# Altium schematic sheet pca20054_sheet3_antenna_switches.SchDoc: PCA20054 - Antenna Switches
size A2; Organization: Nordic Semiconductor; DocumentNumber: 0; Revision: 1.0.0; SheetNumber: 3; SheetTotal: 5; CompanyName: Nordic Semiconductor; DrawnBy: KJP; DocumentSize: A2; Project Number: 4467
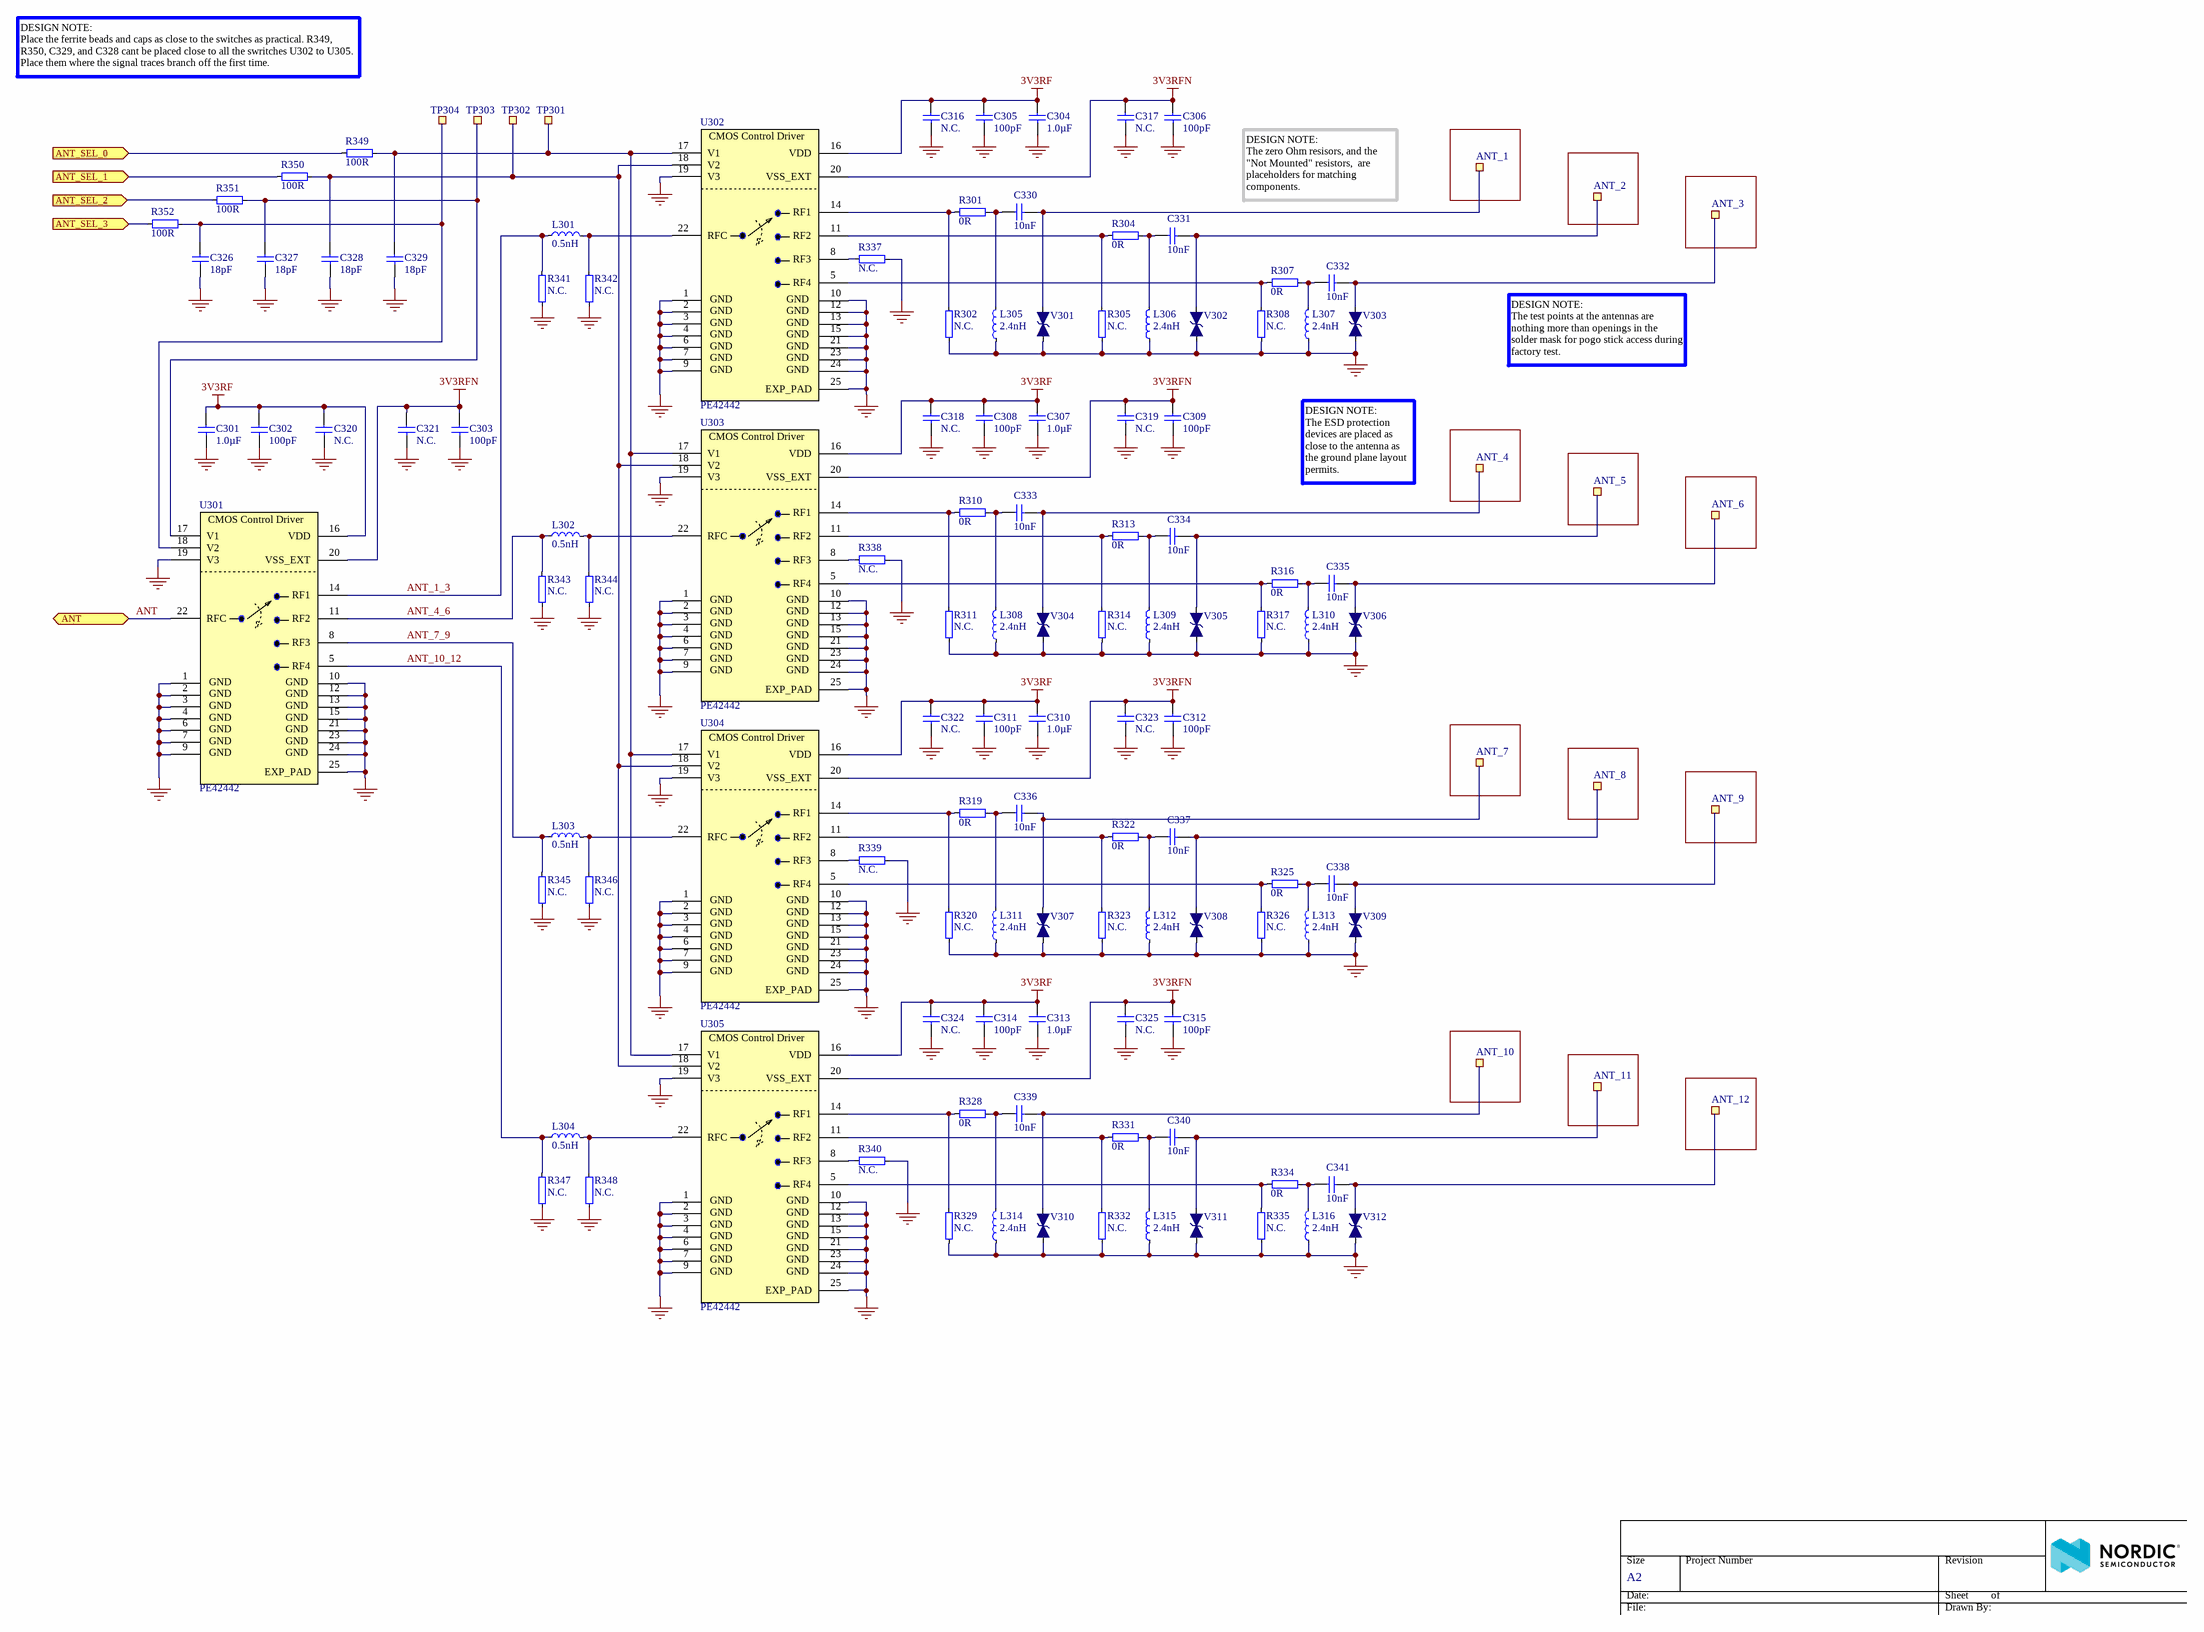
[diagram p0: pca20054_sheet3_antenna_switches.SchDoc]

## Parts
ANT_1  Ø1.0mm,SMD  [TP_SMD_Ø1.0mm]  (value not drawn)  (no BOM)
ANT_2  Ø1.0mm,SMD  [TP_SMD_Ø1.0mm]  (value not drawn)  (no BOM)
ANT_3  Ø1.0mm,SMD  [TP_SMD_Ø1.0mm]  (value not drawn)  (no BOM)
ANT_4  Ø1.0mm,SMD  [TP_SMD_Ø1.0mm]  (value not drawn)  (no BOM)
ANT_5  Ø1.0mm,SMD  [TP_SMD_Ø1.0mm]  (value not drawn)  (no BOM)
ANT_6  Ø1.0mm,SMD  [TP_SMD_Ø1.0mm]  (value not drawn)  (no BOM)
ANT_7  Ø1.0mm,SMD  [TP_SMD_Ø1.0mm]  (value not drawn)  (no BOM)
ANT_8  Ø1.0mm,SMD  [TP_SMD_Ø1.0mm]  (value not drawn)  (no BOM)
ANT_9  Ø1.0mm,SMD  [TP_SMD_Ø1.0mm]  (value not drawn)  (no BOM)
ANT_10  Ø1.0mm,SMD  [TP_SMD_Ø1.0mm]  (value not drawn)  (no BOM)
ANT_11  Ø1.0mm,SMD  [TP_SMD_Ø1.0mm]  (value not drawn)  (no BOM)
ANT_12  Ø1.0mm,SMD  [TP_SMD_Ø1.0mm]  (value not drawn)  (no BOM)
C301  1.0µF  [CAPC1608X06L]
C302  100pF  [CAPC1005X04L]
C303  100pF  [CAPC1005X04L]
C304  1.0µF  [CAPC1608X06L]
C305  100pF  [CAPC1005X04L]
C306  100pF  [CAPC1005X04L]
C307  1.0µF  [CAPC1608X06L]
C308  100pF  [CAPC1005X04L]
C309  100pF  [CAPC1005X04L]
C310  1.0µF  [CAPC1608X06L]
C311  100pF  [CAPC1005X04L]
C312  100pF  [CAPC1005X04L]
C313  1.0µF  [CAPC1608X06L]
C314  100pF  [CAPC1005X04L]
C315  100pF  [CAPC1005X04L]
C316  N.C.  [CAPC1005X04L_NC]
C317  N.C.  [CAPC1005X04L_NC]
C318  N.C.  [CAPC1005X04L_NC]
C319  N.C.  [CAPC1005X04L_NC]
C320  N.C.  [CAPC1005X04L_NC]
C321  N.C.  [CAPC1005X04L_NC]
C322  N.C.  [CAPC1005X04L_NC]
C323  N.C.  [CAPC1005X04L_NC]
C324  N.C.  [CAPC1005X04L_NC]
C325  N.C.  [CAPC1005X04L_NC]
C326  18pF  [CAPC1005X04L]
C327  18pF  [CAPC1005X04L]
C328  18pF  [CAPC1005X04L]
C329  18pF  [CAPC1005X04L]
C330  10nF  [CAPC1005X04L]
C331  10nF  [CAPC1005X04L]
C332  10nF  [CAPC1005X04L]
C333  10nF  [CAPC1005X04L]
C334  10nF  [CAPC1005X04L]
C335  10nF  [CAPC1005X04L]
C336  10nF  [CAPC1005X04L]
C337  10nF  [CAPC1005X04L]
C338  10nF  [CAPC1005X04L]
C339  10nF  [CAPC1005X04L]
C340  10nF  [CAPC1005X04L]
C341  10nF  [CAPC1005X04L]
L301  0.5nH  [INDC1005X04L]
L302  0.5nH  [INDC1005X04L]
L303  0.5nH  [INDC1005X04L]
L304  0.5nH  [INDC1005X04L]
L305  2.4nH  [INDC1005X04L]
L306  2.4nH  [INDC1005X04L]
L307  2.4nH  [INDC1005X04L]
L308  2.4nH  [INDC1005X04L]
L309  2.4nH  [INDC1005X04L]
L310  2.4nH  [INDC1005X04L]
L311  2.4nH  [INDC1005X04L]
L312  2.4nH  [INDC1005X04L]
L313  2.4nH  [INDC1005X04L]
L314  2.4nH  [INDC1005X04L]
L315  2.4nH  [INDC1005X04L]
L316  2.4nH  [INDC1005X04L]
R301  0R  [RESC1005X04L]
R302  N.C.  [RESC1005X04L_NC]
R304  0R  [RESC1005X04L]
R305  N.C.  [RESC1005X04L_NC]
R307  0R  [RESC1005X04L]
R308  N.C.  [RESC1005X04L_NC]
R310  0R  [RESC1005X04L]
R311  N.C.  [RESC1005X04L_NC]
R313  0R  [RESC1005X04L]
R314  N.C.  [RESC1005X04L_NC]
R316  0R  [RESC1005X04L]
R317  N.C.  [RESC1005X04L_NC]
R319  0R  [RESC1005X04L]
R320  N.C.  [RESC1005X04L_NC]
R322  0R  [RESC1005X04L]
R323  N.C.  [RESC1005X04L_NC]
R325  0R  [RESC1005X04L]
R326  N.C.  [RESC1005X04L_NC]
R328  0R  [RESC1005X04L]
R329  N.C.  [RESC1005X04L_NC]
R331  0R  [RESC1005X04L]
R332  N.C.  [RESC1005X04L_NC]
R334  0R  [RESC1005X04L]
R335  N.C.  [RESC1005X04L_NC]
R337  N.C.  [RESC1005X04L_NC]
R338  N.C.  [RESC1005X04L_NC]
R339  N.C.  [RESC1005X04L_NC]
R340  N.C.  [RESC1005X04L_NC]
R341  N.C.  [RESC1005X04L_NC]
R342  N.C.  [RESC1005X04L_NC]
R343  N.C.  [RESC1005X04L_NC]
R344  N.C.  [RESC1005X04L_NC]
R345  N.C.  [RESC1005X04L_NC]
R346  N.C.  [RESC1005X04L_NC]
R347  N.C.  [RESC1005X04L_NC]
R348  N.C.  [RESC1005X04L_NC]
R349  100R  [RESC1005X04L]
R350  100R  [RESC1005X04L]
R351  100R  [RESC1005X04L]
R352  100R  [RESC1005X04L]
TP301  Ø1.0mm,SMD  [TP_SMD_Ø1.0mm]  (value not drawn)  (no BOM)
TP302  Ø1.0mm,SMD  [TP_SMD_Ø1.0mm]  (value not drawn)  (no BOM)
TP303  Ø1.0mm,SMD  [TP_SMD_Ø1.0mm]  (value not drawn)  (no BOM)
TP304  Ø1.0mm,SMD  [TP_SMD_Ø1.0mm]  (value not drawn)  (no BOM)
U301  PE42442  [QFN50P400X400X80_HS-25N]
U302  PE42442  [QFN50P400X400X80_HS-25N]
U303  PE42442  [QFN50P400X400X80_HS-25N]
U304  PE42442  [QFN50P400X400X80_HS-25N]
U305  PE42442  [QFN50P400X400X80_HS-25N]
V301  LXES15AAA1-133  [RESC1005X04L]  (value not drawn)
V302  LXES15AAA1-133  [RESC1005X04L]  (value not drawn)
V303  LXES15AAA1-133  [RESC1005X04L]  (value not drawn)
V304  LXES15AAA1-133  [RESC1005X04L]  (value not drawn)
V305  LXES15AAA1-133  [RESC1005X04L]  (value not drawn)
V306  LXES15AAA1-133  [RESC1005X04L]  (value not drawn)
V307  LXES15AAA1-133  [RESC1005X04L]  (value not drawn)
V308  LXES15AAA1-133  [RESC1005X04L]  (value not drawn)
V309  LXES15AAA1-133  [RESC1005X04L]  (value not drawn)
V310  LXES15AAA1-133  [RESC1005X04L]  (value not drawn)
V311  LXES15AAA1-133  [RESC1005X04L]  (value not drawn)
V312  LXES15AAA1-133  [RESC1005X04L]  (value not drawn)

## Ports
ANT (bidir), ANT_SEL_0 (in), ANT_SEL_1 (in), ANT_SEL_2 (in), ANT_SEL_3 (in)

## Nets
3V3RF: C301.2 C302.2 C304.2 C305.2 C307.2 C308.2 C310.2 C311.2 C313.2 C314.2 C316.2 C318.2 C320.2 C322.2 C324.2 U301.16(VDD) U302.16(VDD) U303.16(VDD) U304.16(VDD) U305.16(VDD)
3V3RFN: C303.2 C306.2 C309.2 C312.2 C315.2 C317.2 C319.2 C321.2 C323.2 C325.2 U301.20(VSS_EXT) U302.20(VSS_EXT) U303.20(VSS_EXT) U304.20(VSS_EXT) U305.20(VSS_EXT)
GND: C301.1 C302.1 C303.1 C304.1 C305.1 C306.1 C307.1 C308.1 C309.1 C310.1 C311.1 C312.1 C313.1 C314.1 C315.1 C316.1 C317.1 C318.1 C319.1 C320.1 C321.1 C322.1 C323.1 C324.1 C325.1 C326.1 C327.1 C328.1 C329.1 L305.1 L306.1 L307.1 L308.1 L309.1 L310.1 L311.1 L312.1 L313.1 L314.1 L315.1 L316.1 R302.1 R305.1 R308.1 R311.1 R314.1 R317.1 R320.1 R323.1 R326.1 R329.1 R332.1 R335.1 R337.2 R338.2 R339.2 R340.2 R341.1 R342.1 R343.1 R344.1 R345.1 R346.1 R347.1 R348.1 U301.1(GND1) U301.2(GND2) U301.3(GND3) U301.4(GND4) U301.6(GND5) U301.7(GND6) U301.9(GND7) U301.10(GND8) U301.12(GND9) U301.13(GND10) U301.15(GND11) U301.19(V3) U301.21(GND12) U301.23(GND14) U301.24(GND13) U301.25(EXP_PAD) U302.1(GND1) U302.2(GND2) U302.3(GND3) U302.4(GND4) U302.6(GND5) U302.7(GND6) U302.9(GND7) U302.10(GND8) U302.12(GND9) U302.13(GND10) U302.15(GND11) U302.19(V3) U302.21(GND12) U302.23(GND14) U302.24(GND13) U302.25(EXP_PAD) U303.1(GND1) U303.2(GND2) U303.3(GND3) U303.4(GND4) U303.6(GND5) U303.7(GND6) U303.9(GND7) U303.10(GND8) U303.12(GND9) U303.13(GND10) U303.15(GND11) U303.19(V3) U303.21(GND12) U303.23(GND14) U303.24(GND13) U303.25(EXP_PAD) U304.1(GND1) U304.2(GND2) U304.3(GND3) U304.4(GND4) U304.6(GND5) U304.7(GND6) U304.9(GND7) U304.10(GND8) U304.12(GND9) U304.13(GND10) U304.15(GND11) U304.19(V3) U304.21(GND12) U304.23(GND14) U304.24(GND13) U304.25(EXP_PAD) U305.1(GND1) U305.2(GND2) U305.3(GND3) U305.4(GND4) U305.6(GND5) U305.7(GND6) U305.9(GND7) U305.10(GND8) U305.12(GND9) U305.13(GND10) U305.15(GND11) U305.19(V3) U305.21(GND12) U305.23(GND14) U305.24(GND13) U305.25(EXP_PAD) V301.2 V302.2 V303.2 V304.2 V305.2 V306.2 V307.2 V308.2 V309.2 V310.2 V311.2 V312.2
ANT: U301.22(RFC) ; port ANT
ANT_1_3: L301.1 R341.2 U301.14(RF1)
ANT_4_6: L302.1 R343.2 U301.11(RF2)
ANT_7_9: L303.1 R345.2 U301.8(RF3)
ANT_10_12: L304.1 R347.2 U301.5(RF4)
ANT_SEL_0: R349.1 ; port ANT_SEL_0
ANT_SEL_1: R350.1 ; port ANT_SEL_1
ANT_SEL_2: R351.1 ; port ANT_SEL_2
ANT_SEL_3: R352.1 ; port ANT_SEL_3
NetANT_1_1: ANT_1.1 C330.2 V301.1
NetANT_2_1: ANT_2.1 C331.2 V302.1
NetANT_3_1: ANT_3.1 C332.2 V303.1
NetANT_4_1: ANT_4.1 C333.2 V304.1
NetANT_5_1: ANT_5.1 C334.2 V305.1
NetANT_6_1: ANT_6.1 C335.2 V306.1
NetANT_7_1: ANT_7.1 C336.2 V307.1
NetANT_8_1: ANT_8.1 C337.2 V308.1
NetANT_9_1: ANT_9.1 C338.2 V309.1
NetANT_10_1: ANT_10.1 C339.2 V310.1
NetANT_11_1: ANT_11.1 C340.2 V311.1
NetANT_12_1: ANT_12.1 C341.2 V312.1
NetC326_2: C326.2 R352.2 TP304.1 U301.18(V2)
NetC327_2: C327.2 R351.2 TP303.1 U301.17(V1)
NetC328_2: C328.2 R350.2 TP302.1 U302.18(V2) U303.18(V2) U304.18(V2) U305.18(V2)
NetC329_2: C329.2 R349.2 TP301.1 U302.17(V1) U303.17(V1) U304.17(V1) U305.17(V1)
NetC330_1: C330.1 L305.2 R301.2
NetC331_1: C331.1 L306.2 R304.2
NetC332_1: C332.1 L307.2 R307.2
NetC333_1: C333.1 L308.2 R310.2
NetC334_1: C334.1 L309.2 R313.2
NetC335_1: C335.1 L310.2 R316.2
NetC336_1: C336.1 L311.2 R319.2
NetC337_1: C337.1 L312.2 R322.2
NetC338_1: C338.1 L313.2 R325.2
NetC339_1: C339.1 L314.2 R328.2
NetC340_1: C340.1 L315.2 R331.2
NetC341_1: C341.1 L316.2 R334.2
NetL301_2: L301.2 R342.2 U302.22(RFC)
NetL302_2: L302.2 R344.2 U303.22(RFC)
NetL303_2: L303.2 R346.2 U304.22(RFC)
NetL304_2: L304.2 R348.2 U305.22(RFC)
NetR301_1: R301.1 R302.2 U302.14(RF1)
NetR304_1: R304.1 R305.2 U302.11(RF2)
NetR307_1: R307.1 R308.2 U302.5(RF4)
NetR310_1: R310.1 R311.2 U303.14(RF1)
NetR313_1: R313.1 R314.2 U303.11(RF2)
NetR316_1: R316.1 R317.2 U303.5(RF4)
NetR319_1: R319.1 R320.2 U304.14(RF1)
NetR322_1: R322.1 R323.2 U304.11(RF2)
NetR325_1: R325.1 R326.2 U304.5(RF4)
NetR328_1: R328.1 R329.2 U305.14(RF1)
NetR331_1: R331.1 R332.2 U305.11(RF2)
NetR334_1: R334.1 R335.2 U305.5(RF4)
NetR337_1: R337.1 U302.8(RF3)
NetR338_1: R338.1 U303.8(RF3)
NetR339_1: R339.1 U304.8(RF3)
NetR340_1: R340.1 U305.8(RF3)

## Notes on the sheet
- DESIGN NOTE:
  Place the ferrite beads and caps as close to the switches as practical. R349, R350, C329, and C328 cant be placed close to all the swritches U302 to U305. Place them where the signal traces branch off the first time.
- DESIGN NOTE:
  The zero Ohm resisors, and the "Not Mounted" resistors,  are placeholders for matching components.
- DESIGN NOTE:
  The test points at the antennas are nothing more than openings in the solder mask for pogo stick access during factory test.
- DESIGN NOTE:
  The ESD protection devices are placed as close to the antenna as the ground plane layout permits.
- Size
- Date:
- File:
- A2
- Project Number
- Sheet         of
- Drawn By:
- Revision

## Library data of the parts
ANT_1-ANT_12 TP301-TP304 = TP_SMD_Ø1.0MM: 1.0mm circular SMD testpad; Manufacturer: Nordic Semiconductor; Artikkelnr Noca: N.A.
C301 C304 C307 C310 C313 = C0603-1µ0: Capacitor, X7R, ±10%; Part number IPS: 00000000616; Note: 16V; Artikkelnr Noca: 20039282
C302 C303 C305 C306 C308 C309 C311 C312 C314 C315 = C0402-100p: Capacitor, NP0, ±5%; Part number IPS: 00000002361; Note: 50V; Artikkelnr Noca: 20029135
C316-C325 = C0402-N.C.: Not mounted; Assembly: Not mounted; Note: Chip Cap; Artikkelnr Noca: N.A.
C326-C329 = C0402-18p: Capacitor, NP0, ±5%; Part number IPS: N.A.; Note: 50V; Artikkelnr Noca: 20029209
C330-C341 = C0402-10n: Capacitor, X7R, ±10%; Part number IPS: 00000007784; Note: 16V; Artikkelnr Noca: 20039166
L301-L304 = L0402-0n5: Inductor, 1A, ±0.1nH; Manufacturer: TDK Corporation; Manufacturer Part Number: MLG1005S0N5BT000; Note: High frequency chip inductor ±0.1nH; Artikkelnr Noca: N.A.
L305-L316 = L0402-2n4: Inductor, 220mA, ±0.1nH; Part number IPS: N.A.; Note: High frequency chip inductor ±5%
R301 R304 R307 R310 R313 R316 R319 R322 R325 R328 R331 R334 = R0402-0R: Resistor, ±5%, 0.063W; Part number IPS: 00000007128; Note: Chip Res 5%; Artikkelnr Noca: 27049000
R302 R305 R308 R311 R314 R317 R320 R323 R326 R329 R332 R335 R337-R348 = R0402-N.C.: Not mounted; Assembly: Not mounted; Note: Chip Res; Artikkelnr Noca: N.A.
R349-R352 = R0402-100: Resistor, ±1%, 0.063W; Part number IPS: 00000002811; Note: Chip Res 1%; Artikkelnr Noca: 27049049
U301-U305 = PE42442: UltraCMOS SP4T RF Switch 30 MHz-6 GHz; Manufacturer: Peregrine Semiconductors; Artikkelnr Noca: N.A.
V301-V312 = LXES15AAA1-133: TVS DIODE 15VWM 0402; Manufacturer: Murata; Artikkelnr Noca: N.A.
